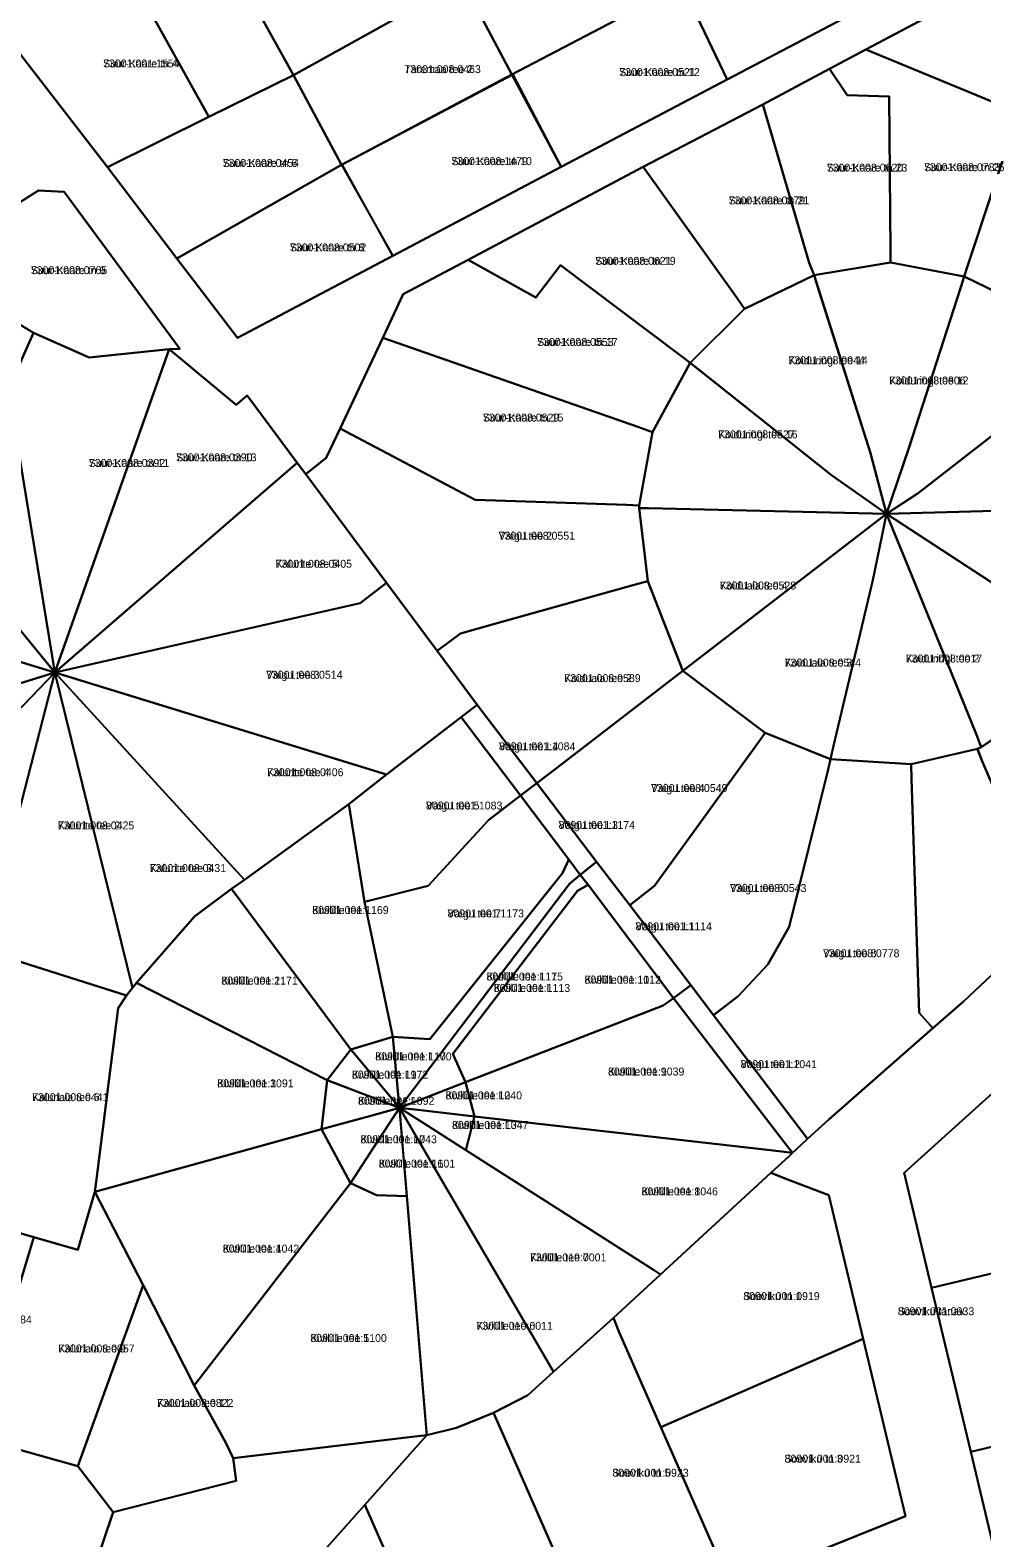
# Model space of a CAD drawing. Extents: x 524000 to 564260, y 6469338 to 6496391.
# Drawn here: x 534922.8 to 535103.4, y 6471171.7 to 6471457.7 of the extents above; entities that cross this region are included whole.
import ezdxf

# ---------------------------------------------------------------- set-up
doc = ezdxf.new("R2010")
doc.units = 0
for name, color, linetype in [('L_AADRESS', 7, 'Continuous'), ('PIIR', 7, 'Continuous'), ('TUNNUS', 7, 'Continuous')]:
    doc.layers.add(name, color=color, linetype=linetype)

msp = doc.modelspace()

# ---------------------------------------------------------------- linework, layer by layer
at = {"layer": 'PIIR'}
for points in [[(534916.54, 6471458.66), (534937.41, 6471431.74), (534950.58, 6471414.37), (534962.09, 6471399.34), (534991.61, 6471414.89), (535023.58, 6471431.75), (535055.09, 6471448.37), (535091.5, 6471467.54), (535126.57, 6471486.46), (535159.68, 6471504.02), (535191.18, 6471520.22), (535210.24, 6471529.29), (535241.75, 6471540.33), (535247.59, 6471543.86), (535250.1, 6471545.38), (535261.82, 6471554.07), (535267.84, 6471559.35), (535273.45, 6471564.87), (535279.87, 6471571.42)], [(535142.93, 6471486.63), (535081.36, 6471454.06), (535074.51, 6471450.4), (535061.86, 6471443.63), (535039.13, 6471431.78), (535005.88, 6471414.16), (534993.58, 6471407.6), (534989.73, 6471399.36), (534981.62, 6471382.14), (534978.95, 6471376.56), (534975.07, 6471373.46), (534973.45, 6471375.63), (534963.93, 6471388.42), (534961.87, 6471386.63), (534949.13, 6471397.18), (534951.16, 6471397.25), (534929.19, 6471427.05), (534924.35, 6471427.26), (534917.14, 6471422.73)], [(535055.78, 6471162.45), (535088.9, 6471175.76), (535080.87, 6471209.43), (535074.39, 6471236.66), (535066.71, 6471239.6), (535063.35, 6471240.89), (535066.71, 6471243.98), (535067.48, 6471244.71), (535070.03, 6471247.13), (535070.32, 6471247.39), (535074.38, 6471251.05), (535094.08, 6471268.34), (535099.9, 6471273.45), (535111.6, 6471284.39)], [(535115.83, 6471265.42), (535088.68, 6471240.93), (535093.88, 6471219.11), (535101.31, 6471187.99), (535108.73, 6471156.85)]]:
    msp.add_lwpolyline(points, dxfattribs=at)
for points in [[(534972.76, 6471449.14), (534956.6, 6471478.28), (534989.46, 6471495.91), (535004.84, 6471466.98)], [(535142.93, 6471486.63), (535146.89, 6471478), (535112.06, 6471441.27), (535110.36, 6471442.07), (535081.36, 6471454.06)], [(535004.84, 6471466.98), (535036.86, 6471484), (535046.52, 6471466.25), (535014.22, 6471449.3)], [(535046.52, 6471466.25), (535082.03, 6471485.35), (535091.5, 6471467.54), (535055.09, 6471448.37)], [(534956.69, 6471441.26), (534940.48, 6471470.42), (534956.6, 6471478.28), (534972.76, 6471449.14)], [(534956.69, 6471441.26), (534937.41, 6471431.74), (534916.54, 6471458.66), (534940.48, 6471470.42)], [(534972.76, 6471449.14), (535004.84, 6471466.98), (535014.22, 6471449.3), (534981.86, 6471432.14)], [(535014.22, 6471449.3), (535046.52, 6471466.25), (535055.09, 6471448.37), (535023.58, 6471431.75)], [(535086.08, 6471415.91), (535085.82, 6471445.13), (535077.85, 6471445.39), (535074.51, 6471450.4), (535081.36, 6471454.06), (535110.36, 6471442.07), (535100.78, 6471413.1), (535100.08, 6471410.99), (535086.1, 6471413.64)], [(534937.41, 6471431.74), (534956.69, 6471441.26), (534972.76, 6471449.14), (534981.86, 6471432.14), (534950.58, 6471414.37)], [(534982, 6471432.19), (535014.36, 6471449.32), (535023.58, 6471431.75), (534991.61, 6471414.89)], [(535070.63, 6471413.55), (535061.86, 6471443.63), (535074.51, 6471450.4), (535077.85, 6471445.39), (535085.82, 6471445.13), (535086.08, 6471415.91), (535086.1, 6471413.64), (535071.56, 6471411.22)], [(535061.86, 6471443.63), (535070.63, 6471413.55), (535071.56, 6471411.22), (535058.36, 6471404.86), (535056.95, 6471406.84), (535039.13, 6471431.78)], [(535100.78, 6471413.1), (535110.36, 6471442.07), (535112.06, 6471441.27), (535132.44, 6471432.22), (535114.44, 6471406.73), (535112.99, 6471404.68), (535100.08, 6471410.99)], [(534950.58, 6471414.37), (534981.86, 6471432.14), (534991.61, 6471414.89), (534962.09, 6471399.34)], [(535018.72, 6471406.96), (535005.88, 6471414.16), (535039.13, 6471431.78), (535056.95, 6471406.84), (535058.36, 6471404.86), (535048.07, 6471394.6), (535046.22, 6471396), (535023.42, 6471413.14)], [(534900.66, 6471420.51), (534917.14, 6471422.73), (534924.35, 6471427.26), (534929.19, 6471427.05), (534951.16, 6471397.25), (534949.13, 6471397.18), (534933.99, 6471395.58), (534923.42, 6471400.31), (534897.68, 6471415.89)], [(534886.94, 6471385.29), (534897.68, 6471415.89), (534923.42, 6471400.31), (534918.64, 6471389.57), (534927.44, 6471335.81)], [(534993.58, 6471407.6), (535005.88, 6471414.16), (535018.72, 6471406.96), (535023.42, 6471413.14), (535046.22, 6471396), (535048.07, 6471394.6), (535040.89, 6471381.45), (535038.12, 6471382.42), (534989.73, 6471399.36)], [(535074.87, 6471373.25), (535048.07, 6471394.6), (535058.36, 6471404.86), (535071.56, 6471411.22), (535082.27, 6471377.44), (535085.33, 6471365.94)], [(535082.27, 6471377.44), (535072.15, 6471409.34), (535071.56, 6471411.22), (535086.1, 6471413.64), (535100.08, 6471410.99), (535099.4, 6471408.93), (535089.55, 6471378.42), (535085.33, 6471365.94)], [(535085.33, 6471365.94), (535089.55, 6471378.42), (535099.4, 6471408.93), (535100.08, 6471410.99), (535112.99, 6471404.68), (535123.43, 6471394.83), (535121.22, 6471393.11), (535091.33, 6471369.86)], [(534918.64, 6471389.57), (534923.42, 6471400.31), (534933.99, 6471395.58), (534949.13, 6471397.18), (534927.44, 6471335.81)], [(534949.13, 6471397.18), (534961.87, 6471386.63), (534963.93, 6471388.42), (534973.45, 6471375.63), (534968.85, 6471371.66), (534927.44, 6471335.81)], [(534981.62, 6471382.14), (534989.73, 6471399.36), (535038.12, 6471382.42), (535040.89, 6471381.45), (535038.38, 6471367.55), (535035.97, 6471367.63), (535007.24, 6471368.58)], [(535038.37, 6471367.05), (535038.38, 6471367.55), (535040.89, 6471381.45), (535048.07, 6471394.6), (535049.52, 6471393.45), (535074.87, 6471373.25), (535085.33, 6471365.94), (535040.16, 6471367.01)], [(535091.33, 6471369.86), (535121.22, 6471393.11), (535123.43, 6471394.83), (535124.05, 6471394.29), (535131.08, 6471382.5), (535133.16, 6471367.28), (535131.04, 6471367.23), (535085.33, 6471365.94)], [(534875.27, 6471351.81), (534885.21, 6471385.79), (534886.94, 6471385.29), (534927.44, 6471335.81), (534877, 6471351.28)], [(534990.4, 6471352.86), (534975.07, 6471373.46), (534978.95, 6471376.56), (534981.62, 6471382.14), (535007.24, 6471368.58), (535035.97, 6471367.63), (535038.38, 6471367.55), (535038.37, 6471367.05), (535040.01, 6471353.19), (535037.4, 6471352.46), (535010.69, 6471345.02), (535004.43, 6471343.26), (534999.99, 6471339.95)], [(534968.85, 6471371.66), (534973.45, 6471375.63), (534975.07, 6471373.46), (534990.4, 6471352.86), (534985.38, 6471348.99), (534927.44, 6471335.81)], [(535040.16, 6471367.01), (535085.33, 6471365.94), (535046.63, 6471336.13), (535040.01, 6471353.19), (535038.37, 6471367.05)], [(535046.63, 6471336.13), (535085.33, 6471365.94), (535082.72, 6471353.34), (535075.22, 6471321.92), (535074.65, 6471319.38), (535062.31, 6471324.41)], [(535090.03, 6471354.36), (535102.32, 6471324.2), (535103.29, 6471321.67), (535102.56, 6471321.37), (535089.99, 6471318.45), (535074.65, 6471319.38), (535075.22, 6471321.92), (535082.72, 6471353.34), (535085.33, 6471365.94)], [(535131.04, 6471367.23), (535133.16, 6471367.28), (535131.53, 6471352.81), (535125.3, 6471339.83), (535123, 6471341.33), (535085.33, 6471365.94)], [(535102.32, 6471324.2), (535090.03, 6471354.36), (535085.33, 6471365.94), (535123, 6471341.33), (535125.3, 6471339.83), (535115, 6471329.3), (535103.29, 6471321.67)], [(534864.69, 6471317.65), (534875.27, 6471351.81), (534877, 6471351.28), (534927.44, 6471335.81), (534866.89, 6471316.99)], [(534985.38, 6471348.99), (534990.4, 6471352.86), (534999.99, 6471339.95), (535007.6, 6471329.72), (535002.4, 6471325.7), (534990.39, 6471316.46), (534927.44, 6471335.81)], [(535018.94, 6471314.84), (535007.6, 6471329.72), (534999.99, 6471339.95), (535004.43, 6471343.26), (535010.69, 6471345.02), (535037.4, 6471352.46), (535040.01, 6471353.19), (535046.63, 6471336.13), (535023.47, 6471318.3)], [(534859.9, 6471300.4), (534864.69, 6471317.65), (534866.89, 6471316.99), (534927.44, 6471335.81), (534885.56, 6471292.27), (534881.82, 6471293.39), (534861.63, 6471299.84)], [(534885.56, 6471292.27), (534927.44, 6471335.81), (534913.83, 6471283.22), (534900.88, 6471287.32)], [(534942.2, 6471276.03), (534941.06, 6471274.53), (534919.94, 6471281.26), (534913.83, 6471283.22), (534927.44, 6471335.81)], [(534990.39, 6471316.46), (534983.23, 6471310.84), (534963.46, 6471296.53), (534927.44, 6471335.81)], [(534927.44, 6471335.81), (534963.46, 6471296.53), (534961.01, 6471294.79), (534953.98, 6471289.55), (534942.97, 6471276.95), (534942.2, 6471276.03)], [(535036.56, 6471291.7), (535030.28, 6471299.94), (535018.94, 6471314.84), (535023.47, 6471318.3), (535046.63, 6471336.13), (535062.31, 6471324.41), (535061.22, 6471322.9), (535041.27, 6471295.34)], [(535004.56, 6471327.37), (535007.6, 6471329.72), (535018.94, 6471314.84), (535015.85, 6471312.49)], [(535115.28, 6471291.49), (535103.48, 6471319.05), (535102.67, 6471321.1), (535102.56, 6471321.37), (535103.29, 6471321.67), (535114.81, 6471329.5), (535115, 6471329.3), (535139.74, 6471303.06), (535125.64, 6471294.25), (535116.71, 6471288.2)], [(535002.4, 6471325.7), (535004.56, 6471327.37), (535015.85, 6471312.49), (535009.77, 6471307.82), (534998.28, 6471295.39), (534986.25, 6471292.32), (534983.23, 6471310.84), (534990.39, 6471316.46)], [(535036.56, 6471291.7), (535041.27, 6471295.34), (535061.22, 6471322.9), (535062.31, 6471324.41), (535074.65, 6471319.38), (535074.21, 6471317.42), (535066.86, 6471287.58), (535062.78, 6471280.44), (535057.13, 6471274.44), (535052.46, 6471270.82), (535048.15, 6471276.49)], [(535111.6, 6471284.39), (535099.9, 6471273.45), (535094.08, 6471268.34), (535091.5, 6471271.3), (535090.08, 6471315.59), (535089.99, 6471318.45), (535102.56, 6471321.37), (535103.48, 6471319.05), (535115.28, 6471291.49), (535116.71, 6471288.2), (535116.59, 6471288.12)], [(535052.46, 6471270.82), (535057.13, 6471274.44), (535062.78, 6471280.44), (535066.86, 6471287.58), (535074.21, 6471317.42), (535074.65, 6471319.38), (535089.99, 6471318.45), (535090.08, 6471315.59), (535091.5, 6471271.3), (535094.08, 6471268.34), (535074.38, 6471251.05), (535070.32, 6471247.39), (535068.75, 6471249.44)], [(535015.85, 6471312.49), (535018.94, 6471314.84), (535030.28, 6471299.94), (535027.19, 6471297.43), (535025.01, 6471300.34)], [(535009.77, 6471307.82), (535015.85, 6471312.49), (535025.01, 6471300.34), (535023.84, 6471297.79), (534998.6, 6471266.27), (534991.62, 6471266.69), (534986.25, 6471292.32), (534998.28, 6471295.39)], [(534983.66, 6471264.34), (534961.01, 6471294.79), (534963.46, 6471296.53), (534983.23, 6471310.84), (534986.25, 6471292.32), (534991.62, 6471266.69)], [(535023.84, 6471297.79), (535025.01, 6471300.34), (535027.19, 6471297.43), (535025.13, 6471295.76), (534994.39, 6471255.27), (534992.86, 6471253.26), (534992.63, 6471255.71), (534991.62, 6471266.69), (534998.6, 6471266.27)], [(535027.19, 6471297.43), (535030.28, 6471299.94), (535036.56, 6471291.7), (535048.15, 6471276.49), (535044.89, 6471274.06), (535028.66, 6471295.53)], [(535025.13, 6471295.76), (535027.19, 6471297.43), (535028.66, 6471295.53), (535026.66, 6471294.45), (535002.99, 6471263.49), (535005.38, 6471258.09), (534995.63, 6471254.33), (534992.86, 6471253.26), (534994.39, 6471255.27)], [(534953.98, 6471289.55), (534961.01, 6471294.79), (534983.66, 6471264.34), (534979.15, 6471258.48), (534942.97, 6471276.95)], [(535026.66, 6471294.45), (535028.66, 6471295.53), (535044.89, 6471274.06), (535042.94, 6471272.65), (535005.38, 6471258.09), (535002.99, 6471263.49)], [(534941.06, 6471274.53), (534939.48, 6471272.15), (534937.72, 6471258.32), (534935.29, 6471239.21), (534935.04, 6471237.33), (534931.84, 6471226.29), (534923.45, 6471228.7), (534905.2, 6471233.96), (534919.94, 6471281.26)], [(534942.2, 6471276.03), (534942.97, 6471276.95), (534979.15, 6471258.48), (534978.06, 6471249.17), (534935.04, 6471237.33), (534935.29, 6471239.21), (534937.72, 6471258.32), (534939.48, 6471272.15), (534941.06, 6471274.53)], [(535042.94, 6471272.65), (535044.89, 6471274.06), (535065.89, 6471246.73), (535067.48, 6471244.71), (535063.82, 6471245.13), (535007.1, 6471251.63), (535005.38, 6471258.09)], [(535044.89, 6471274.06), (535048.15, 6471276.49), (535052.46, 6471270.82), (535068.75, 6471249.44), (535070.32, 6471247.39), (535070.03, 6471247.13), (535067.48, 6471244.71), (535065.89, 6471246.73)], [(535132.89, 6471228.42), (535093.88, 6471219.11), (535088.68, 6471240.93), (535115.83, 6471265.42), (535122.77, 6471270.89), (535127.21, 6471252.24)], [(534990.77, 6471255.79), (534983.66, 6471264.34), (534991.62, 6471266.69), (534992.63, 6471255.71), (534992.86, 6471253.26)], [(534989.06, 6471254.71), (534979.15, 6471258.48), (534983.66, 6471264.34), (534990.77, 6471255.79), (534992.86, 6471253.26)], [(534987.43, 6471251.75), (534978.06, 6471249.17), (534979.15, 6471258.48), (534989.06, 6471254.71), (534992.86, 6471253.26)], [(534995.63, 6471254.33), (535005.38, 6471258.09), (535007.1, 6471251.63), (534996.9, 6471252.8), (534992.86, 6471253.26)], [(534988.82, 6471247.04), (534983.59, 6471238.97), (534978.06, 6471249.17), (534987.43, 6471251.75), (534992.86, 6471253.26)], [(534993.53, 6471245.26), (534994.26, 6471236.49), (534988.5, 6471236.65), (534983.59, 6471238.97), (534988.82, 6471247.04), (534992.86, 6471253.26)], [(534998.24, 6471249.82), (535005.48, 6471245.19), (535041.08, 6471222.5), (535042.42, 6471221.65), (535033.46, 6471213.4), (535022.11, 6471203.15), (535021.32, 6471204.5), (534992.86, 6471253.26)], [(535003.67, 6471192.55), (534998.08, 6471191.16), (534997.84, 6471193.35), (534992.86, 6471253.26), (535021.32, 6471204.5), (535022.11, 6471203.15), (535017.23, 6471198.75), (535010.74, 6471195.39)], [(534996.9, 6471252.8), (535007.1, 6471251.63), (535005.48, 6471245.19), (534998.24, 6471249.82), (534992.86, 6471253.26)], [(535005.48, 6471245.19), (535007.1, 6471251.63), (535063.82, 6471245.13), (535067.48, 6471244.71), (535066.71, 6471243.98), (535063.35, 6471240.89), (535042.42, 6471221.65), (535041.08, 6471222.5)], [(534935.04, 6471237.33), (534978.06, 6471249.17), (534983.59, 6471238.97), (534953.88, 6471200.54), (534944.19, 6471219.61)], [(535063.35, 6471240.89), (535066.71, 6471239.6), (535074.39, 6471236.66), (535080.87, 6471209.43), (535042.47, 6471192.67), (535034.53, 6471210.79), (535033.46, 6471213.4), (535042.42, 6471221.65)], [(534923.45, 6471228.7), (534931.84, 6471226.29), (534935.04, 6471237.33), (534944.19, 6471219.61), (534931.84, 6471185.26), (534918.53, 6471188.99), (534911.99, 6471190.75)], [(534953.88, 6471200.54), (534983.59, 6471238.97), (534988.5, 6471236.65), (534994.26, 6471236.49), (534997.86, 6471193.12), (534998.03, 6471191.15), (534995.78, 6471190.9), (534961.3, 6471186.81), (534959.82, 6471189.79)], [(534905.2, 6471233.96), (534923.45, 6471228.7), (534911.99, 6471190.75), (534893.68, 6471195.81)], [(535140.31, 6471197.27), (535101.31, 6471187.99), (535093.88, 6471219.11), (535132.89, 6471228.42), (535133.61, 6471225.44), (535139.85, 6471199.15)], [(534931.8, 6471185.27), (534944.19, 6471219.61), (534953.88, 6471200.54), (534959.82, 6471189.79), (534961.3, 6471186.81), (534961.89, 6471182.45), (534938.53, 6471176.53)], [(535042.47, 6471192.67), (535055.78, 6471162.45), (535029.8, 6471151.9), (535011.98, 6471192.56), (535010.74, 6471195.39), (535017.23, 6471198.75), (535022.11, 6471203.15), (535033.46, 6471213.4), (535034.53, 6471210.79)], [(535042.47, 6471192.67), (535080.87, 6471209.43), (535088.9, 6471175.76), (535055.78, 6471162.45)], [(535147.73, 6471166.16), (535108.73, 6471156.85), (535101.31, 6471187.99), (535140.31, 6471197.27), (535146.09, 6471173.04)], [(535011.98, 6471192.56), (535029.8, 6471151.9), (535002.52, 6471140.89), (534986.27, 6471177.92), (534995.4, 6471188.16), (534998.03, 6471191.15), (535003.67, 6471192.55), (535010.74, 6471195.39)], [(534929.17, 6471127.81), (534923.35, 6471129.83), (534932.7, 6471159.28), (534938.53, 6471176.53), (534961.89, 6471182.45), (534961.3, 6471186.81), (534995.78, 6471190.9), (534998.03, 6471191.15), (534995.4, 6471188.16), (534986.27, 6471177.92), (534974.91, 6471165.15), (534963.01, 6471151.8), (534961.44, 6471145.95), (534937.27, 6471152.88)], [(534869.4, 6471143.24), (534880.5, 6471153.54), (534918.53, 6471188.99), (534931.8, 6471185.27), (534938.53, 6471176.53), (534932.7, 6471159.28), (534884.38, 6471147.21)], [(534986.27, 6471177.92), (535002.52, 6471140.89), (534988.1, 6471135.06), (534974.91, 6471165.15)]]:
    msp.add_lwpolyline(points, close=True, dxfattribs=at)

# ---------------------------------------------------------------- texts
at = {"layer": 'L_AADRESS'}
for s, p in [('Suur-Kaare tn 4', (534936.61, 6471450.64)), ('Taremaa tee 2', (534993.8, 6471449.56)), ('Suur-Kaare tn 12', (535034.58, 6471449)), ('Suur-Kaare tn 6', (534959.31, 6471431.76)), ('Suur-Kaare tn 10', (535002.72, 6471432.11)), ('Suur-Kaare tn 23', (535073.98, 6471430.87)), ('Suur-Kaare tn 25', (535092.43, 6471430.96)), ('Suur-Kaare tn 21', (535055.35, 6471424.66)), ('Suur-Kaare tn 8', (534972.06, 6471415.74)), ('Suur-Kaare tn 19', (535030.01, 6471413.19)), ('Suur-Kaare tn 9', (534922.89, 6471411.42)), ('Suur-Kaare tn 17', (535019, 6471397.8)), ('Koiduringi tee 14', (535066.7, 6471394.32)), ('Koiduringi tee 12', (535085.82, 6471390.49)), ('Suur-Kaare tn 15', (535008.7, 6471383.46)), ('Koiduringi tee 16', (535053.37, 6471380.27)), ('Suur-Kaare tn 13', (534950.45, 6471375.91)), ('Suur-Kaare tn 11', (534933.89, 6471374.84)), ('Vaigu tee 2', (535011.69, 6471361.04)), ('Kalurite tee 5', (534969.35, 6471355.72)), ('Koiduaia tee 4', (535053.67, 6471351.59)), ('Koiduaia tee 3', (535065.98, 6471336.97)), ('Koiduringi tee 2', (535088.97, 6471337.74)), ('Vaigu tee 3', (534967.55, 6471334.66)), ('Koiduaia tee 2', (535024.14, 6471334.02)), ('Vaigu tee L4', (535011.75, 6471321.08)), ('Kalurite tee 4', (534967.74, 6471316.17)), ('Vaigu tee 4', (535040.62, 6471313.17)), ('Vaigu tee 5', (534997.9, 6471309.85)), ('Kalurite tee 2', (534928.02, 6471306.08)), ('Vaigu tee L3', (535023.07, 6471306.17)), ('Kalurite tee 3', (534945.45, 6471297.98)), ('Vaigu tee 6', (535055.61, 6471294.2)), ('Kivilille tee 1', (534976.31, 6471290.02)), ('Vaigu tee 7', (535001.99, 6471289.38)), ('Vaigu tee L1', (535037.67, 6471286.93)), ('Vaigu tee 8', (535073.27, 6471281.83)), ('Kivilille tee 2', (534959.05, 6471276.63)), ('Kivilille tee L11', (535009.4, 6471277.41)), ('Kivilille tee L1', (535010.76, 6471275.24)), ('Kivilille tee 10', (535027.99, 6471276.81)), ('Kivilille tee L10', (534988.26, 6471262.25)), ('Vaigu tee L2', (535057.61, 6471260.79)), ('Kivilille tee L9', (534983.83, 6471258.8)), ('Kivilille tee 9', (535032.44, 6471259.38)), ('Kivilille tee 3', (534958.28, 6471257.14)), ('Kaluriaia tee 6', (534923.13, 6471254.52)), ('Kivilille tee L8', (534984.99, 6471253.83)), ('Kivilille tee L2', (535001.62, 6471254.86)), ('Kivilille tee L7', (534985.46, 6471246.53)), ('Kivilille tee L3', (535002.83, 6471249.23)), ('Kivilille tee L6', (534988.93, 6471241.92)), ('Kivilille tee 8', (535038.81, 6471236.64)), ('Kivilille tee 4', (534959.32, 6471225.79)), ('Kivilille tee 7', (535017.64, 6471224.12)), ('Sooviku tn 1', (535058.13, 6471216.78)), ('Sooviku tänav', (535087.46, 6471213.91)), ('Kivilille tee 6', (535007.48, 6471211.14)), ('Kaluriaia tee 9', (534928.09, 6471206.84)), ('Kivilille tee 5', (534975.96, 6471208.82)), ('Kaluriaia tee 11', (534946.84, 6471196.51)), ('Sooviku tn 3', (535065.95, 6471185.94)), ('Sooviku tn 5', (535033.26, 6471183.26))]:
    msp.add_text(s, height=1.5, dxfattribs=at).set_placement(p)
at = {"layer": 'TUNNUS'}
for s, p in [('73001:001:1554', (534936.61, 6471450.64)), ('73001:008:0463', (534993.8, 6471449.56)), ('73001:008:0521', (535034.58, 6471449)), ('73001:008:0454', (534959.31, 6471431.76)), ('73001:008:1479', (535002.72, 6471432.11)), ('73001:008:0620', (535073.98, 6471430.87)), ('73001:008:0783', (535092.43, 6471430.96)), ('73001:008:0879', (535055.35, 6471424.66)), ('73001:008:0502', (534972.06, 6471415.74)), ('73001:008:0621', (535030.01, 6471413.19)), ('73001:008:0765', (534922.89, 6471411.42)), ('73001:008:0553', (535019, 6471397.8)), ('73001:008:0944', (535066.7, 6471394.32)), ('73001:008:0806', (535085.82, 6471390.49)), ('73001:008:0529', (535008.7, 6471383.46)), ('73001:008:0527', (535053.37, 6471380.27)), ('73001:008:0390', (534950.45, 6471375.91)), ('73001:008:0392', (534933.89, 6471374.84)), ('73001:008:0551', (535011.69, 6471361.04)), ('73001:008:0405', (534969.35, 6471355.72)), ('73001:008:0528', (535053.67, 6471351.59)), ('73001:008:0544', (535065.98, 6471336.97)), ('73001:008:0017', (535088.97, 6471337.74)), ('73001:008:0514', (534967.55, 6471334.66)), ('73001:008:0589', (535024.14, 6471334.02)), ('80901:001:1084', (535011.75, 6471321.08)), ('73001:008:0406', (534967.74, 6471316.17)), ('73001:008:0549', (535040.62, 6471313.17)), ('80901:001:1083', (534997.9, 6471309.85)), ('73001:008:0425', (534928.02, 6471306.08)), ('80901:001:1174', (535023.07, 6471306.17)), ('73001:008:0431', (534945.45, 6471297.98)), ('73001:008:0543', (535055.61, 6471294.2)), ('80901:001:1169', (534976.31, 6471290.02)), ('80901:001:1173', (535001.99, 6471289.38)), ('80901:001:1114', (535037.67, 6471286.93)), ('73001:008:0778', (535073.27, 6471281.83)), ('80901:001:1171', (534959.05, 6471276.63)), ('80901:001:1175', (535009.4, 6471277.41)), ('80901:001:1113', (535010.76, 6471275.24)), ('80901:001:1112', (535027.99, 6471276.81)), ('80901:001:1170', (534988.26, 6471262.25)), ('80901:001:1041', (535057.61, 6471260.79)), ('80901:001:1172', (534983.83, 6471258.8)), ('80901:001:1039', (535032.44, 6471259.38)), ('80901:001:1091', (534958.28, 6471257.14)), ('73001:008:0441', (534923.13, 6471254.52)), ('80901:001:1092', (534984.99, 6471253.83)), ('80901:001:1040', (535001.62, 6471254.86)), ('80901:001:1043', (534985.46, 6471246.53)), ('80901:001:1047', (535002.83, 6471249.23)), ('80901:001:1101', (534988.93, 6471241.92)), ('80901:001:1046', (535038.81, 6471236.64)), ('80901:001:1042', (534959.32, 6471225.79)), ('73001:010:0001', (535017.64, 6471224.12)), ('80901:001:0919', (535058.13, 6471216.78)), ('73001:008:0384', (534908.57, 6471212.34)), ('80901:001:0933', (535087.46, 6471213.91)), ('73001:010:0011', (535007.48, 6471211.14)), ('73001:008:0057', (534928.09, 6471206.84)), ('80901:001:1100', (534975.96, 6471208.82)), ('73001:008:0822', (534946.84, 6471196.51)), ('80901:001:0921', (535065.95, 6471185.94)), ('80901:001:0923', (535033.26, 6471183.26))]:
    msp.add_text(s, height=1.5, dxfattribs=at).set_placement(p)

doc.saveas('drawing.dxf')
